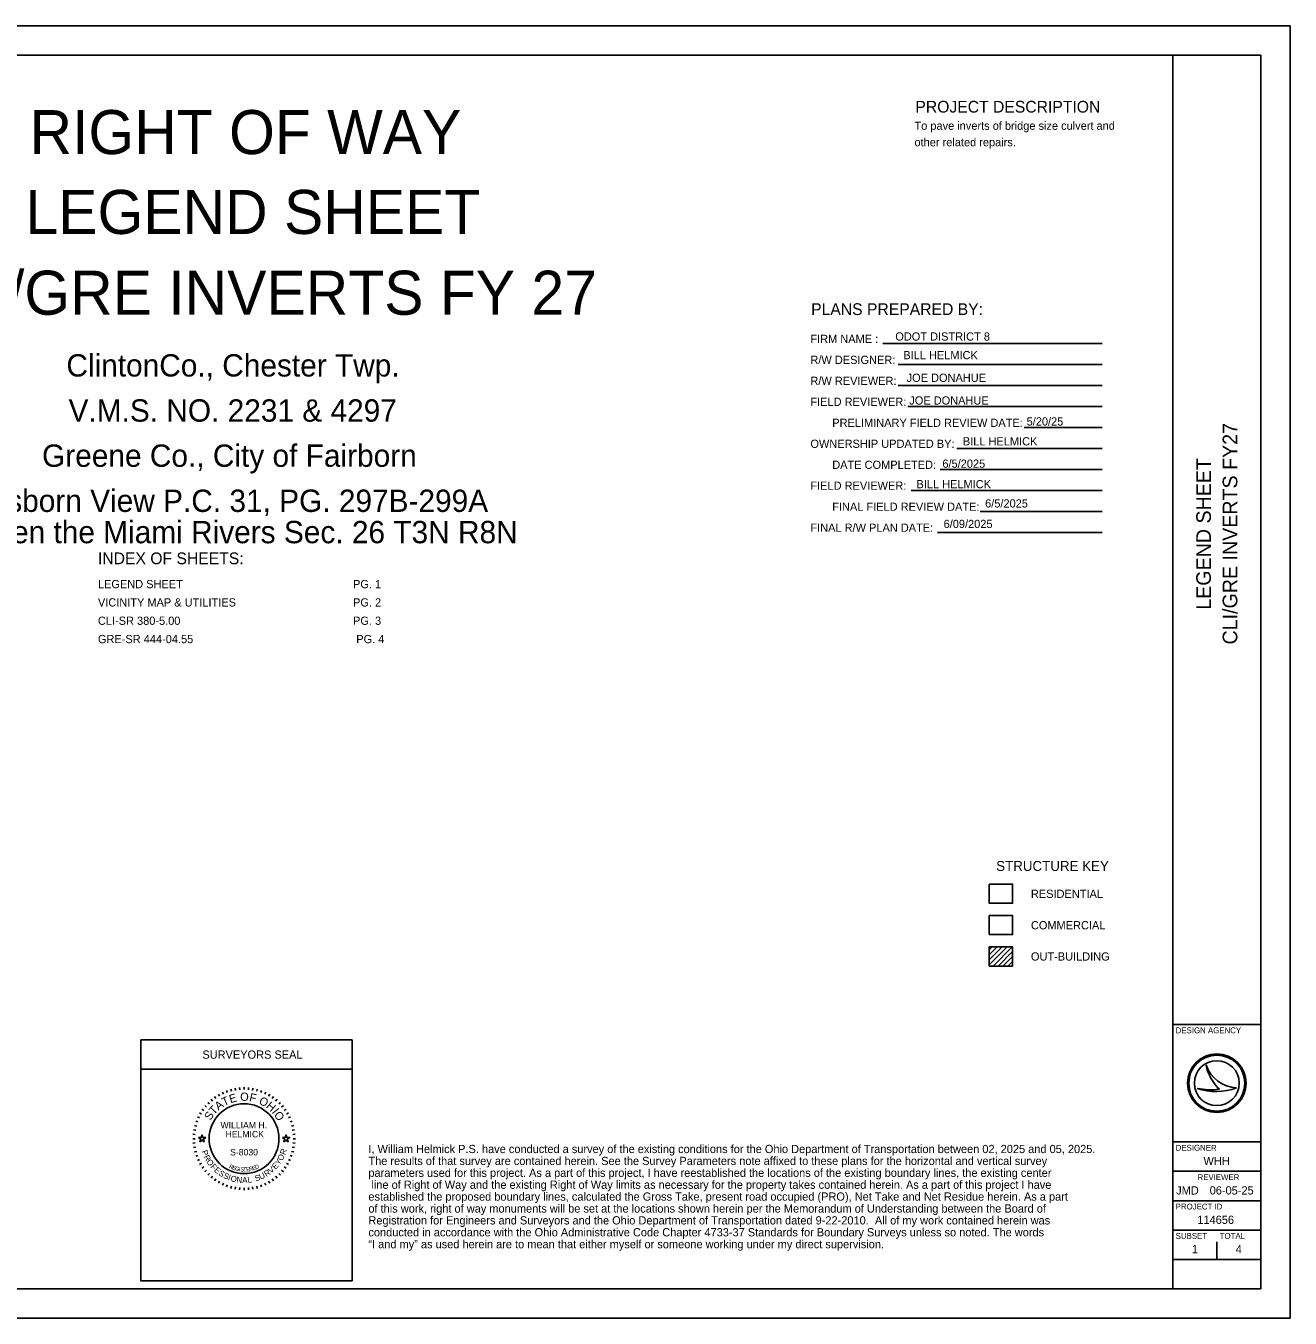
# Model space of a CAD drawing. Extents: x 0 to 34, y 0 to 22.
# Drawn here: x 12.46 to 34, y 0 to 22 of the extents above; entities that cross this region are included whole.
import ezdxf

# ---------------------------------------------------------------- set-up
doc = ezdxf.new("R2010")
doc.units = 0
for name, color, linetype in [('Default', 7, 'Continuous'), ('SC_Shading1', 7, 'Continuous'), ('SH_Border', 7, 'Continuous'), ('SH_Cut_Line', 7, 'Continuous'), ('SH_Data', 7, 'Continuous'), ('SH_Seal', 7, 'Continuous'), ('SH_Text', 7, 'Continuous')]:
    doc.layers.add(name, color=color, linetype=linetype)

msp = doc.modelspace()

# ---------------------------------------------------------------- linework, layer by layer
at = {"layer": 'SC_Shading1'}
msp.add_lwpolyline([(28.875, 6.529), (29.272, 6.529), (29.272, 6.854), (28.875, 6.854)], close=True, dxfattribs=at)
at = {"layer": 'SH_Border'}
for p, q in [((32, 0.5), (32, 21.5)), ((32, 5), (33.5, 5)), ((32, 3), (33.5, 3)), ((32, 2.5), (33.5, 2.5)), ((32, 2), (33.5, 2)), ((32, 1.5), (33.5, 1.5)), ((32, 1), (33.5, 1))]:
    msp.add_line(p, q, dxfattribs=at)
msp.add_lwpolyline([(1.5, 21.5), (33.5, 21.5), (33.5, 0.5), (1.5, 0.5)], close=True, dxfattribs=at)
at = {"layer": 'SH_Cut_Line'}
msp.add_lwpolyline([(0, 0), (34, 0), (34, 22), (0, 22)], close=True, dxfattribs=at)
at = {"layer": 'SH_Data'}
for p, q in [((14.422, 4.237), (18.022, 4.237)), ((32.567, 4.31), (32.567, 4.31)), ((32.75, 4), (32.75, 4)), ((32.417, 3.91), (32.417, 3.91)), ((33.087, 3.919), (33.087, 3.919)), ((32.75, 1), (32.75, 1.3))]:
    msp.add_line(p, q, dxfattribs=at)
msp.add_lwpolyline([(14.422, 4.737), (18.022, 4.737), (18.022, 0.637), (14.422, 0.637)], close=True, dxfattribs=at)
for radius in [0.5, 0.477, 0.477, 0.382]:
    msp.add_circle((32.75, 4), radius, dxfattribs=at)
for centre, radius, start, end in [((33.116, 4.498), 0.58, 198.9257, 198.9319), ((33.347, 4.47), 0.796, 191.6379, 191.6421), ((33.116, 4.498), 0.58, 198.9319, 267.1657), ((33.347, 4.47), 0.796, 191.6421, 226.0947), ((32.739, 4.87), 1.013, 251.4576, 290.0832), ((32.648, 5.154), 1.266, 259.4964, 259.4995), ((32.739, 4.87), 1.013, 251.4527, 251.4576), ((32.648, 5.154), 1.266, 259.4995, 276.6672)]:
    msp.add_arc(centre, radius, start, end, dxfattribs=at)
at = {"layer": 'SH_Seal'}
for p, q in [((15.679, 3.772), (15.702, 3.739)), ((15.743, 3.813), (15.763, 3.778)), ((15.811, 3.848), (15.828, 3.812)), ((15.881, 3.878), (15.895, 3.84)), ((15.954, 3.9), (15.965, 3.862)), ((16.029, 3.917), (16.036, 3.878)), ((16.104, 3.927), (16.108, 3.887)), ((16.181, 3.93), (16.181, 3.89)), ((16.257, 3.927), (16.254, 3.887)), ((16.333, 3.917), (16.326, 3.878)), ((16.407, 3.9), (16.397, 3.862)), ((16.48, 3.878), (16.466, 3.84)), ((16.551, 3.848), (16.534, 3.812)), ((16.618, 3.813), (16.598, 3.778)), ((16.683, 3.772), (16.66, 3.739)), ((15.464, 3.557), (15.497, 3.534)), ((15.51, 3.618), (15.541, 3.592)), ((15.562, 3.674), (15.59, 3.646)), ((15.618, 3.726), (15.644, 3.695)), ((16.743, 3.726), (16.717, 3.695)), ((16.799, 3.674), (16.771, 3.646)), ((16.851, 3.618), (16.82, 3.592)), ((16.898, 3.557), (16.865, 3.534)), ((15.359, 3.355), (15.396, 3.341)), ((15.388, 3.425), (15.424, 3.408)), ((15.423, 3.493), (15.458, 3.473)), ((16.939, 3.493), (16.904, 3.473)), ((16.974, 3.425), (16.938, 3.408)), ((17.003, 3.355), (16.965, 3.341)), ((15.309, 3.132), (15.349, 3.128)), ((15.319, 3.207), (15.358, 3.2)), ((15.336, 3.282), (15.374, 3.271)), ((17.026, 3.282), (16.987, 3.271)), ((17.042, 3.207), (17.003, 3.2)), ((17.052, 3.132), (17.013, 3.128)), ((15.306, 3.055), (15.346, 3.055)), ((15.309, 2.979), (15.349, 2.982)), ((15.319, 2.903), (15.358, 2.91)), ((17.042, 2.903), (17.003, 2.91)), ((17.052, 2.979), (17.013, 2.982)), ((17.056, 3.055), (17.016, 3.055)), ((15.336, 2.829), (15.374, 2.839)), ((15.359, 2.756), (15.396, 2.77)), ((15.388, 2.685), (15.424, 2.702)), ((16.974, 2.685), (16.938, 2.702)), ((17.003, 2.756), (16.965, 2.77)), ((17.026, 2.829), (16.987, 2.839)), ((15.423, 2.618), (15.458, 2.638)), ((15.464, 2.553), (15.497, 2.576)), ((15.51, 2.493), (15.541, 2.519)), ((15.562, 2.437), (15.59, 2.465)), ((16.799, 2.437), (16.771, 2.465)), ((16.851, 2.493), (16.82, 2.519)), ((16.898, 2.553), (16.865, 2.576)), ((16.939, 2.618), (16.904, 2.638)), ((15.618, 2.385), (15.644, 2.416)), ((15.679, 2.339), (15.702, 2.371)), ((15.743, 2.298), (15.763, 2.332)), ((15.811, 2.262), (15.828, 2.299)), ((15.881, 2.233), (15.895, 2.271)), ((15.954, 2.21), (15.965, 2.249)), ((16.029, 2.194), (16.036, 2.233)), ((16.104, 2.184), (16.108, 2.223)), ((16.181, 2.18), (16.181, 2.22)), ((16.257, 2.184), (16.254, 2.223)), ((16.333, 2.194), (16.326, 2.233)), ((16.407, 2.21), (16.397, 2.249)), ((16.48, 2.233), (16.466, 2.271)), ((16.551, 2.262), (16.534, 2.299)), ((16.618, 2.298), (16.598, 2.332)), ((16.683, 2.339), (16.66, 2.371)), ((16.743, 2.385), (16.717, 2.416))]:
    msp.add_line(p, q, dxfattribs=at)
for points in [[(15.404, 3.075), (15.451, 3.075), (15.466, 3.12), (15.48, 3.075), (15.527, 3.075), (15.489, 3.048), (15.504, 3.003), (15.466, 3.031), (15.428, 3.003), (15.442, 3.048)], [(16.834, 3.075), (16.881, 3.075), (16.896, 3.12), (16.91, 3.075), (16.957, 3.075), (16.919, 3.048), (16.934, 3.003), (16.896, 3.031), (16.858, 3.003), (16.872, 3.048)]]:
    msp.add_lwpolyline(points, close=True, dxfattribs=at)
msp.add_circle((16.181, 3.055), 0.595, dxfattribs=at)
at = {"layer": 'SH_Text'}
for p, q in [((27.06, 16.592), (30.797, 16.592)), ((27.324, 16.234), (30.797, 16.234)), ((27.324, 15.877), (30.797, 15.877)), ((27.488, 15.52), (30.797, 15.52)), ((29.47, 15.163), (30.797, 15.163)), ((28.324, 14.806), (30.797, 14.806)), ((28.039, 14.448), (30.797, 14.448)), ((27.542, 14.092), (30.797, 14.092)), ((28.722, 13.734), (30.797, 13.734)), ((27.994, 13.377), (30.797, 13.377)), ((28.875, 6.318), (28.876, 6.319)), ((28.875, 6.268), (28.926, 6.319)), ((28.875, 6.183), (29.011, 6.319)), ((28.875, 6.098), (29.096, 6.319)), ((28.875, 6.014), (29.18, 6.319)), ((28.939, 5.993), (29.265, 6.319)), ((29.024, 5.993), (29.272, 6.241)), ((28.875, 5.998), (28.879, 5.993)), ((29.108, 5.993), (29.272, 6.157)), ((29.193, 5.993), (29.272, 6.072))]:
    msp.add_line(p, q, dxfattribs=at)
for points in [[(28.875, 7.39), (29.272, 7.39), (29.272, 7.064), (28.875, 7.064)], [(28.875, 6.319), (29.272, 6.319), (29.272, 5.993), (28.875, 5.993)]]:
    msp.add_lwpolyline(points, close=True, dxfattribs=at)

# ---------------------------------------------------------------- texts
at = {"layer": 'Default'}
for s, p in [('ODOT DISTRICT 8', (27.274, 16.642)), ('BILL HELMICK', (27.41, 16.324)), ('JOE DONAHUE', (27.467, 15.939)), ('JOE DONAHUE', (27.512, 15.553)), ('5/20/25', (29.511, 15.195)), ('BILL HELMICK', (28.425, 14.857)), ('6/5/2025', (28.076, 14.477)), ('BILL HELMICK', (27.635, 14.128)), ('6/5/2025', (28.804, 13.8)), ('6/09/2025', (28.097, 13.451))]:
    msp.add_text(s, height=0.14, dxfattribs=at).set_placement(p)
at = {"layer": 'SH_Data'}
for s, height, p in [('RIGHT OF WAY', 0.75, (12.527, 19.816)), ('LEGEND SHEET', 0.75, (12.458, 18.457)), ('  CLI/GRE INVERTS FY 27  ', 0.75, (10.042, 17.082)), ('   ClintonCo., Chester Twp.   ', 0.38, (12.731, 16.03)), (' V.M.S. NO. 2231 & 4297', 0.38, (13.05, 15.262)), (' Greene Co., City of Fairborn ', 0.38, (12.599, 14.493)), (' Osborn View P.C. 31, PG. 297B-299A', 0.38, (11.611, 13.725)), ('Between the Miami Rivers Sec. 26 T3N R8N', 0.38, (10.816, 13.192)), ('INDEX OF SHEETS:', 0.2, (13.692, 12.835)), ('LEGEND SHEET', 0.14, (13.692, 12.427)), ('PG. 1', 0.14, (18.038, 12.427)), ('VICINITY MAP & UTILITIES', 0.14, (13.692, 12.115)), ('PG. 2 ', 0.14, (18.038, 12.115)), ('CLI-SR 380-5.00', 0.14, (13.692, 11.803)), ('PG. 3 ', 0.14, (18.038, 11.803)), ('GRE-SR 444-04.55                   ', 0.14, (13.692, 11.491)), ('PG. 4 ', 0.14, (18.092, 11.491)), ('DESIGN AGENCY', 0.1, (32.05, 4.85)), ('SURVEYORS SEAL', 0.14, (15.471, 4.417)), ('DESIGNER', 0.1, (32.05, 2.85)), ('WHH', 0.14, (32.524, 2.605)), ('REVIEWER', 0.1, (32.422, 2.35)), ('JMD', 0.14, (32.058, 2.105)), ('06-05-25', 0.14, (32.629, 2.105)), ('PROJECT ID', 0.1, (32.05, 1.85)), ('114656', 0.14, (32.419, 1.605)), ('SUBSET', 0.1, (32.05, 1.35)), ('TOTAL', 0.1, (32.8, 1.35)), ('1', 0.14, (32.325, 1.105)), ('4', 0.14, (33.072, 1.105))]:
    msp.add_text(s, height=height, dxfattribs=at).set_placement(p)
for s, p in [('CLI/GRE INVERTS FY27', (33.1, 11.468)), ('LEGEND SHEET', (32.65, 12.06))]:
    msp.add_text(s, height=0.25, rotation=90, dxfattribs=at).set_placement(p)
at = {"layer": 'SH_Seal'}
for s, height, rotation, p in [('T', 0.14, 25.7167, (15.842, 3.607)), ('E', 0.14, 15.7571, (15.949, 3.659)), ('O', 0.14, 359.7812, (16.115, 3.7)), ('F', 0.14, 347.4362, (16.262, 3.697)), ('O', 0.14, 332.2586, (16.421, 3.657)), ('T', 0.14, 46.4344, (15.669, 3.452)), ('A', 0.14, 36.4747, (15.744, 3.533)), ('H', 0.14, 319.9136, (16.544, 3.591)), ('I', 0.14, 308.367, (16.647, 3.504)), ('S', 0.14, 57.1924, (15.609, 3.357)), ('O', 0.14, 303.1491, (16.683, 3.464)), ('P', 0.1, 289.7431, (15.456, 2.839)), ('R', 0.1, 70.983, (16.882, 2.772)), ('R', 0.1, 296.9802, (15.49, 2.748)), ('O', 0.1, 304.7158, (15.534, 2.663)), ('E', 0.1, 48.2687, (16.717, 2.523)), ('Y', 0.1, 55.5058, (16.781, 2.595)), ('O', 0.1, 62.7428, (16.831, 2.669)), ('F', 0.1, 312.956, (15.6, 2.571)), ('E', 0.1, 319.6885, (15.662, 2.506)), ('S', 0.1, 326.9255, (15.736, 2.444)), ('S', 0.1, 334.1626, (15.817, 2.393)), ('I', 0.1, 341.3997, (15.9, 2.353)), ('R', 0.07, 334.487, (15.918, 2.56)), ('O', 0.1, 345.1351, (15.943, 2.337)), ('E', 0.07, 341.04, (15.971, 2.535)), ('G', 0.07, 347.4752, (16.022, 2.517)), ('I', 0.07, 353.7858, (16.09, 2.502)), ('S', 0.07, 356.8926, (16.117, 2.498)), ('T', 0.07, 3.0061, (16.166, 2.494)), ('E', 0.07, 6.0117, (16.22, 2.496)), ('R', 0.07, 11.9184, (16.273, 2.503)), ('E', 0.07, 17.6836, (16.331, 2.515)), ('D', 0.07, 23.3052, (16.382, 2.532)), ('S', 0.1, 18.3234, (16.381, 2.326)), ('U', 0.1, 25.5604, (16.464, 2.354)), ('R', 0.1, 33.296, (16.562, 2.403)), ('V', 0.1, 41.0316, (16.642, 2.456)), ('N', 0.1, 353.3752, (16.047, 2.311)), ('A', 0.1, 1.1108, (16.15, 2.3)), ('L', 0.1, 8.3479, (16.247, 2.302))]:
    msp.add_text(s, height=height, rotation=rotation, dxfattribs=at).set_placement(p)
for s, p in [('WILLIAM H.', (15.78, 3.23)), ('HELMICK', (15.866, 3.077)), ('S-8030', (15.943, 2.77))]:
    msp.add_text(s, height=0.11, dxfattribs=at).set_placement(p)
at = {"layer": 'SH_Text'}
for s, height, p in [('PROJECT DESCRIPTION', 0.2, (27.616, 20.523)), ('To pave inverts of bridge size culvert and ', 0.14, (27.601, 20.23)), ('other related repairs.                     ', 0.14, (27.601, 19.95)), ('PLANS PREPARED BY:', 0.2, (25.84, 17.077)), ('FIRM NAME :', 0.14, (25.828, 16.601)), ('R/W DESIGNER:', 0.14, (25.828, 16.244)), ('R/W REVIEWER:', 0.14, (25.828, 15.887)), ('FIELD REVIEWER:', 0.14, (25.828, 15.53)), ('PRELIMINARY FIELD REVIEW DATE:', 0.14, (26.2, 15.173)), ('OWNERSHIP UPDATED BY:', 0.14, (25.828, 14.816)), ('DATE COMPLETED:', 0.14, (26.2, 14.458)), ('FIELD REVIEWER:', 0.14, (25.828, 14.102)), ('FINAL FIELD REVIEW DATE:', 0.14, (26.2, 13.744)), ('FINAL R/W PLAN DATE:', 0.14, (25.828, 13.387)), ('STRUCTURE KEY', 0.17, (28.992, 7.613)), ('RESIDENTIAL', 0.14, (29.584, 7.154)), ('COMMERCIAL', 0.14, (29.584, 6.619)), ('OUT-BUILDING', 0.14, (29.584, 6.087)), ('I, William Helmick P.S. have conducted a survey of the existing conditions for the Ohio Department of Transportation between 02, 2025 and 05, 2025.  ', 0.14, (18.299, 2.81)), ('The results of that survey are contained herein. See the Survey Parameters note affixed to these plans for the horizontal and vertical survey ', 0.14, (18.299, 2.607)), ('parameters used for this project. As a part of this project, I have reestablished the locations of the existing boundary lines, the existing center', 0.14, (18.299, 2.405)), (' line of Right of Way and the existing Right of Way limits as necessary for the property takes contained herein. As a part of this project I have ', 0.14, (18.299, 2.202)), ('established the proposed boundary lines, calculated the Gross Take, present road occupied (PRO), Net Take and Net Residue herein. As a part ', 0.14, (18.299, 2)), ('of this work, right of way monuments will be set at the locations shown herein per the Memorandum of Understanding between the Board of ', 0.14, (18.299, 1.797)), ('Registration for Engineers and Surveyors and the Ohio Department of Transportation dated 9-22-2010.  All of my work contained herein was ', 0.14, (18.299, 1.595)), ('“I and my” as used herein are to mean that either myself or someone working under my direct supervision.', 0.14, (18.299, 1.19)), ('conducted in accordance with the Ohio Administrative Code Chapter 4733-37 Standards for Boundary Surveys unless so noted. The words ', 0.14, (18.299, 1.392))]:
    msp.add_text(s, height=height, dxfattribs=at).set_placement(p)

doc.saveas('drawing.dxf')
